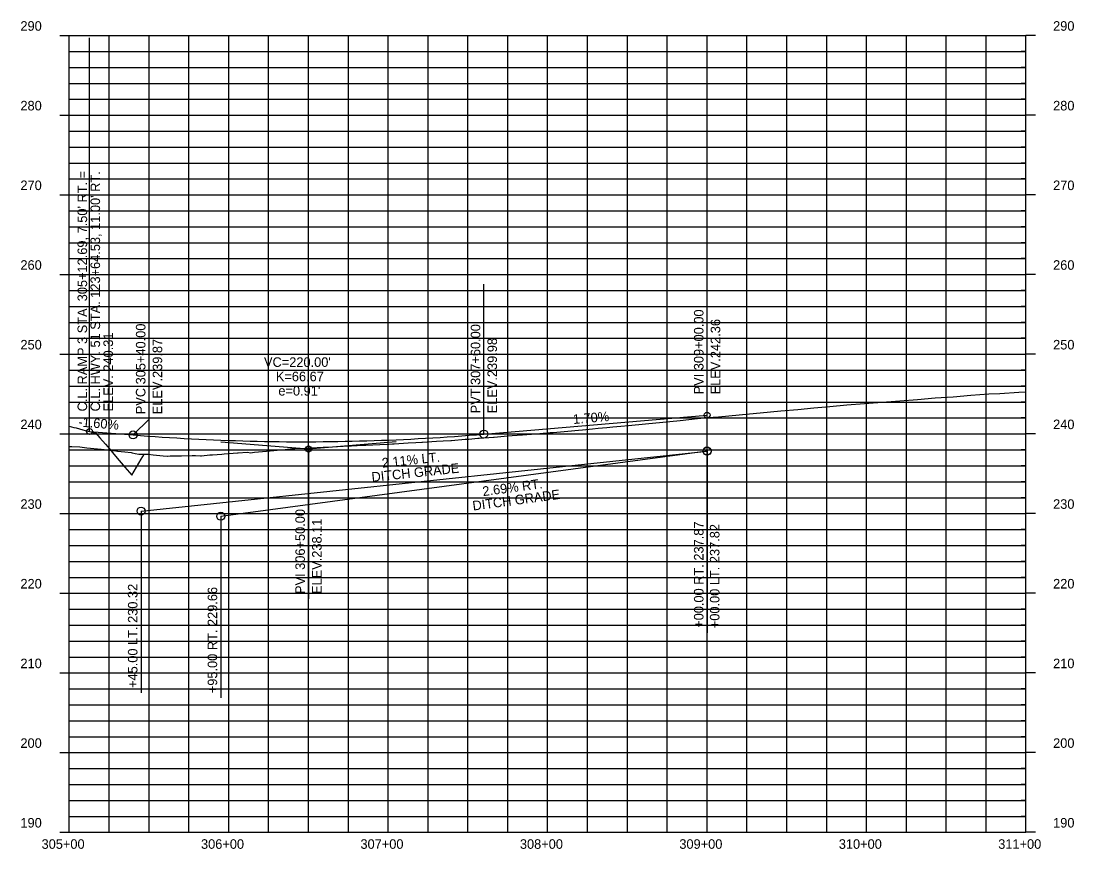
# Model space of a CAD drawing. Extents: x 921603 to 924670, y 1759276 to 1766491.
# Drawn here: x 921610 to 922270, y 1761922 to 1762441 of the extents above; entities that cross this region are included whole.
import ezdxf

# ---------------------------------------------------------------- set-up
doc = ezdxf.new("R2010")
doc.units = 0
for name, color, linetype in [('63', 7, 'Continuous'), ('R_Axis_Annotation', 7, 'Continuous'), ('R_Exist Surface', 7, 'Continuous'), ('R_Grid', 7, 'Continuous'), ('R_Grid Annot', 7, 'Continuous'), ('R_Grid_Minor', 7, 'Continuous'), ('R_Prop Surface', 7, 'Continuous'), ('R_Vert Alg', 7, 'Continuous'), ('R_Vert Alg Annot', 7, 'Continuous')]:
    doc.layers.add(name, color=color, linetype=linetype)

msp = doc.modelspace()

# ---------------------------------------------------------------- linework, layer by layer
at = {"layer": 'R_Exist Surface'}
msp.add_lwpolyline([(921639.83, 1762174.4), (921641.47, 1762174.35), (921646.42, 1762174.12), (921650.91, 1762173.53), (921659.7, 1762172.76), (921669.09, 1762171.62), (921669.17, 1762171.61), (921669.35, 1762171.59), (921670.13, 1762171.53), (921674.61, 1762171.07), (921678.69, 1762170.66), (921679.22, 1762170.5), (921681.17, 1762170.04), (921683.5, 1762169.65), (921683.64, 1762169.62), (921689.18, 1762169.57), (921692.39, 1762169.23), (921698.65, 1762168.58), (921701.28, 1762168.4), (921701.33, 1762168.4), (921703.16, 1762168.49), (921710.18, 1762168.59), (921716.79, 1762168.68), (921719.07, 1762168.65), (921722.13, 1762168.61), (921722.82, 1762168.54), (921727.96, 1762169.06), (921729.61, 1762169.22), (921735.54, 1762169.66), (921736.85, 1762169.76), (921745.32, 1762170.37), (921745.74, 1762170.4), (921751.33, 1762170.79), (921753.57, 1762170.46), (921754.63, 1762170.57), (921756.01, 1762170.71), (921763.53, 1762171.49), (921768.2, 1762171.95), (921772.42, 1762172.33), (921775.2, 1762172.57), (921779.85, 1762173.04), (921781.31, 1762173.1), (921787.44, 1762173.35), (921790.2, 1762173.48), (921791.52, 1762173.55), (921799.09, 1762173.9), (921802.11, 1762174.03), (921807.7, 1762174.28), (921807.98, 1762174.3), (921815.23, 1762174.73), (921816.87, 1762174.8), (921824.2, 1762175.13), (921825.11, 1762175.19), (921825.77, 1762175.22), (921834.66, 1762175.63), (921840.18, 1762175.88), (921842.58, 1762176.04), (921843.55, 1762176.1), (921852.44, 1762176.68), (921857.06, 1762176.98), (921861.02, 1762177.15), (921861.33, 1762177.17), (921870.22, 1762177.74), (921874.21, 1762178), (921879.12, 1762178.21), (921879.46, 1762178.22), (921888.01, 1762178.87), (921890.45, 1762179.06), (921896.05, 1762179.51), (921896.9, 1762179.58), (921905.79, 1762180.26), (921906.22, 1762180.3), (921912.6, 1762180.82), (921914.68, 1762180.97), (921923.57, 1762181.62), (921924, 1762181.65), (921932.46, 1762182.41), (921932.55, 1762182.42), (921941.36, 1762183.07), (921943.26, 1762183.22), (921950.25, 1762183.85), (921952.49, 1762184.05), (921959.14, 1762184.67), (921961.65, 1762184.91), (921968.03, 1762185.5), (921971.48, 1762185.82), (921976.92, 1762186.33), (921980.8, 1762186.7), (921985.81, 1762187.17), (921990.46, 1762187.6), (922001.25, 1762188.59), (922012.13, 1762189.74), (922022.93, 1762190.73), (922033.8, 1762191.87), (922040.32, 1762192.48), (922046.89, 1762193.08), (922053.43, 1762193.69), (922059.99, 1762194.29), (922066.53, 1762194.9), (922073.09, 1762195.5), (922079.64, 1762196.11), (922086.18, 1762196.7), (922096.65, 1762197.69), (922106.78, 1762198.62), (922116.91, 1762199.56), (922127.38, 1762200.55), (922138.52, 1762201.43), (922149.56, 1762202.25), (922160.65, 1762203.13), (922171.73, 1762203.95), (922182.81, 1762204.81), (922194.13, 1762205.64), (922205.2, 1762206.5), (922216.54, 1762207.33), (922223.4, 1762207.73), (922235.42, 1762208.39), (922239.83, 1762208.65)], dxfattribs=at)
at = {"layer": 'R_Grid'}
for p, q in [((921639.83, 1761932.26), (921639.83, 1762432.26)), ((921639.83, 1762432.26), (922239.83, 1762432.26)), ((921639.83, 1762432.26), (922239.83, 1762432.26)), ((921739.83, 1761932.26), (921739.83, 1762432.26)), ((921839.83, 1761932.26), (921839.83, 1762432.26)), ((921939.83, 1761932.26), (921939.83, 1762432.26)), ((922039.83, 1761932.26), (922039.83, 1762432.26)), ((922139.83, 1761932.26), (922139.83, 1762432.26)), ((922239.83, 1761932.26), (922239.83, 1762432.26)), ((921639.83, 1762382.26), (922239.83, 1762382.26)), ((921639.83, 1762332.26), (922239.83, 1762332.26)), ((921639.83, 1762282.26), (922239.83, 1762282.26)), ((921639.83, 1762232.26), (922239.83, 1762232.26)), ((921639.83, 1762182.26), (922239.83, 1762182.26)), ((921639.83, 1762132.26), (922239.83, 1762132.26)), ((921639.83, 1762082.26), (922239.83, 1762082.26)), ((921639.83, 1762032.26), (922239.83, 1762032.26)), ((921639.83, 1761982.26), (922239.83, 1761982.26)), ((921639.83, 1761932.26), (922239.83, 1761932.26))]:
    msp.add_line(p, q, dxfattribs=at)
at = {"layer": 'R_Grid Annot'}
for p, q in [((921633.83, 1762432.26), (921639.83, 1762432.26)), ((921633.83, 1762432.26), (921639.83, 1762432.26)), ((922245.83, 1762432.26), (922239.83, 1762432.26)), ((922245.83, 1762432.26), (922239.83, 1762432.26)), ((921639.83, 1762422.26), (921642.83, 1762422.26)), ((922239.83, 1762422.26), (922236.83, 1762422.26)), ((921639.83, 1762412.26), (921642.83, 1762412.26)), ((922239.83, 1762412.26), (922236.83, 1762412.26)), ((921639.83, 1762402.26), (921642.83, 1762402.26)), ((922239.83, 1762402.26), (922236.83, 1762402.26)), ((921639.83, 1762392.26), (921642.83, 1762392.26)), ((922239.83, 1762392.26), (922236.83, 1762392.26)), ((921633.83, 1762382.26), (921639.83, 1762382.26)), ((922245.83, 1762382.26), (922239.83, 1762382.26)), ((921639.83, 1762372.26), (921642.83, 1762372.26)), ((922239.83, 1762372.26), (922236.83, 1762372.26)), ((921639.83, 1762362.26), (921642.83, 1762362.26)), ((922239.83, 1762362.26), (922236.83, 1762362.26)), ((921639.83, 1762352.26), (921642.83, 1762352.26)), ((922239.83, 1762352.26), (922236.83, 1762352.26)), ((921639.83, 1762342.26), (921642.83, 1762342.26)), ((922239.83, 1762342.26), (922236.83, 1762342.26)), ((921633.83, 1762332.26), (921639.83, 1762332.26)), ((922245.83, 1762332.26), (922239.83, 1762332.26)), ((921639.83, 1762322.26), (921642.83, 1762322.26)), ((922239.83, 1762322.26), (922236.83, 1762322.26)), ((921639.83, 1762312.26), (921642.83, 1762312.26)), ((922239.83, 1762312.26), (922236.83, 1762312.26)), ((921639.83, 1762302.26), (921642.83, 1762302.26)), ((922239.83, 1762302.26), (922236.83, 1762302.26)), ((921639.83, 1762292.26), (921642.83, 1762292.26)), ((922239.83, 1762292.26), (922236.83, 1762292.26)), ((921633.83, 1762282.26), (921639.83, 1762282.26)), ((922245.83, 1762282.26), (922239.83, 1762282.26)), ((921639.83, 1762272.26), (921642.83, 1762272.26)), ((922239.83, 1762272.26), (922236.83, 1762272.26)), ((921639.83, 1762262.26), (921642.83, 1762262.26)), ((922239.83, 1762262.26), (922236.83, 1762262.26)), ((921639.83, 1762252.26), (921642.83, 1762252.26)), ((922239.83, 1762252.26), (922236.83, 1762252.26)), ((921639.83, 1762242.26), (921642.83, 1762242.26)), ((922239.83, 1762242.26), (922236.83, 1762242.26)), ((921633.83, 1762232.26), (921639.83, 1762232.26)), ((922245.83, 1762232.26), (922239.83, 1762232.26)), ((921639.83, 1762222.26), (921642.83, 1762222.26)), ((922239.83, 1762222.26), (922236.83, 1762222.26)), ((921639.83, 1762212.26), (921642.83, 1762212.26)), ((922239.83, 1762212.26), (922236.83, 1762212.26)), ((921639.83, 1762202.26), (921642.83, 1762202.26)), ((922239.83, 1762202.26), (922236.83, 1762202.26)), ((921639.83, 1762192.26), (921642.83, 1762192.26)), ((922239.83, 1762192.26), (922236.83, 1762192.26)), ((921633.83, 1762182.26), (921639.83, 1762182.26)), ((922245.83, 1762182.26), (922239.83, 1762182.26)), ((921639.83, 1762172.26), (921642.83, 1762172.26)), ((922239.83, 1762172.26), (922236.83, 1762172.26)), ((921639.83, 1762162.26), (921642.83, 1762162.26)), ((922239.83, 1762162.26), (922236.83, 1762162.26)), ((921639.83, 1762152.26), (921642.83, 1762152.26)), ((922239.83, 1762152.26), (922236.83, 1762152.26)), ((921639.83, 1762142.26), (921642.83, 1762142.26)), ((922239.83, 1762142.26), (922236.83, 1762142.26)), ((921633.83, 1762132.26), (921639.83, 1762132.26)), ((922245.83, 1762132.26), (922239.83, 1762132.26)), ((921639.83, 1762122.26), (921642.83, 1762122.26)), ((922239.83, 1762122.26), (922236.83, 1762122.26)), ((921639.83, 1762112.26), (921642.83, 1762112.26)), ((922239.83, 1762112.26), (922236.83, 1762112.26)), ((921639.83, 1762102.26), (921642.83, 1762102.26)), ((922239.83, 1762102.26), (922236.83, 1762102.26)), ((921639.83, 1762092.26), (921642.83, 1762092.26)), ((922239.83, 1762092.26), (922236.83, 1762092.26)), ((921633.83, 1762082.26), (921639.83, 1762082.26)), ((922245.83, 1762082.26), (922239.83, 1762082.26)), ((921639.83, 1762072.26), (921642.83, 1762072.26)), ((922239.83, 1762072.26), (922236.83, 1762072.26)), ((921639.83, 1762062.26), (921642.83, 1762062.26)), ((922239.83, 1762062.26), (922236.83, 1762062.26)), ((921639.83, 1762052.26), (921642.83, 1762052.26)), ((922239.83, 1762052.26), (922236.83, 1762052.26)), ((921639.83, 1762042.26), (921642.83, 1762042.26)), ((922239.83, 1762042.26), (922236.83, 1762042.26)), ((921633.83, 1762032.26), (921639.83, 1762032.26)), ((922245.83, 1762032.26), (922239.83, 1762032.26)), ((921639.83, 1762022.26), (921642.83, 1762022.26)), ((922239.83, 1762022.26), (922236.83, 1762022.26)), ((921639.83, 1762012.26), (921642.83, 1762012.26)), ((922239.83, 1762012.26), (922236.83, 1762012.26)), ((921639.83, 1762002.26), (921642.83, 1762002.26)), ((922239.83, 1762002.26), (922236.83, 1762002.26)), ((921639.83, 1761992.26), (921642.83, 1761992.26)), ((922239.83, 1761992.26), (922236.83, 1761992.26)), ((921633.83, 1761982.26), (921639.83, 1761982.26)), ((922245.83, 1761982.26), (922239.83, 1761982.26)), ((921639.83, 1761972.26), (921642.83, 1761972.26)), ((922239.83, 1761972.26), (922236.83, 1761972.26)), ((921639.83, 1761962.26), (921642.83, 1761962.26)), ((922239.83, 1761962.26), (922236.83, 1761962.26)), ((921639.83, 1761952.26), (921642.83, 1761952.26)), ((922239.83, 1761952.26), (922236.83, 1761952.26)), ((921639.83, 1761942.26), (921642.83, 1761942.26)), ((922239.83, 1761942.26), (922236.83, 1761942.26)), ((921633.83, 1761932.26), (921639.83, 1761932.26)), ((922245.83, 1761932.26), (922239.83, 1761932.26))]:
    msp.add_line(p, q, dxfattribs=at)
at = {"layer": 'R_Grid_Minor'}
for p, q in [((921664.83, 1761932.26), (921664.83, 1762432.26)), ((921689.83, 1761932.26), (921689.83, 1762432.26)), ((921714.83, 1761932.26), (921714.83, 1762432.26)), ((921764.83, 1761932.26), (921764.83, 1762432.26)), ((921789.83, 1761932.26), (921789.83, 1762432.26)), ((921814.83, 1761932.26), (921814.83, 1762432.26)), ((921864.83, 1761932.26), (921864.83, 1762432.26)), ((921889.83, 1761932.26), (921889.83, 1762432.26)), ((921914.83, 1761932.26), (921914.83, 1762432.26)), ((921964.83, 1761932.26), (921964.83, 1762432.26)), ((921989.83, 1761932.26), (921989.83, 1762432.26)), ((922014.83, 1761932.26), (922014.83, 1762432.26)), ((922064.83, 1761932.26), (922064.83, 1762432.26)), ((922089.83, 1761932.26), (922089.83, 1762432.26)), ((922114.83, 1761932.26), (922114.83, 1762432.26)), ((922164.83, 1761932.26), (922164.83, 1762432.26)), ((922189.83, 1761932.26), (922189.83, 1762432.26)), ((922214.83, 1761932.26), (922214.83, 1762432.26)), ((921639.83, 1762422.26), (922239.83, 1762422.26)), ((921639.83, 1762412.26), (922239.83, 1762412.26)), ((921639.83, 1762402.26), (922239.83, 1762402.26)), ((921639.83, 1762392.26), (922239.83, 1762392.26)), ((921639.83, 1762372.26), (922239.83, 1762372.26)), ((921639.83, 1762362.26), (922239.83, 1762362.26)), ((921639.83, 1762352.26), (922239.83, 1762352.26)), ((921639.83, 1762342.26), (922239.83, 1762342.26)), ((921639.83, 1762322.26), (922239.83, 1762322.26)), ((921639.83, 1762312.26), (922239.83, 1762312.26)), ((921639.83, 1762302.26), (922239.83, 1762302.26)), ((921639.83, 1762292.26), (922239.83, 1762292.26)), ((921639.83, 1762272.26), (922239.83, 1762272.26)), ((921639.83, 1762262.26), (922239.83, 1762262.26)), ((921639.83, 1762252.26), (922239.83, 1762252.26)), ((921639.83, 1762242.26), (922239.83, 1762242.26)), ((921639.83, 1762222.26), (922239.83, 1762222.26)), ((921639.83, 1762212.26), (922239.83, 1762212.26)), ((921639.83, 1762202.26), (922239.83, 1762202.26)), ((921639.83, 1762192.26), (922239.83, 1762192.26)), ((921639.83, 1762172.26), (922239.83, 1762172.26)), ((921639.83, 1762162.26), (922239.83, 1762162.26)), ((921639.83, 1762152.26), (922239.83, 1762152.26)), ((921639.83, 1762142.26), (922239.83, 1762142.26)), ((921639.83, 1762122.26), (922239.83, 1762122.26)), ((921639.83, 1762112.26), (922239.83, 1762112.26)), ((921639.83, 1762102.26), (922239.83, 1762102.26)), ((921639.83, 1762092.26), (922239.83, 1762092.26)), ((921639.83, 1762072.26), (922239.83, 1762072.26)), ((921639.83, 1762062.26), (922239.83, 1762062.26)), ((921639.83, 1762052.26), (922239.83, 1762052.26)), ((921639.83, 1762042.26), (922239.83, 1762042.26)), ((921639.83, 1762022.26), (922239.83, 1762022.26)), ((921639.83, 1762012.26), (922239.83, 1762012.26)), ((921639.83, 1762002.26), (922239.83, 1762002.26)), ((921639.83, 1761992.26), (922239.83, 1761992.26)), ((921639.83, 1761972.26), (922239.83, 1761972.26)), ((921639.83, 1761962.26), (922239.83, 1761962.26)), ((921639.83, 1761952.26), (922239.83, 1761952.26)), ((921639.83, 1761942.26), (922239.83, 1761942.26))]:
    msp.add_line(p, q, dxfattribs=at)
at = {"layer": 'R_Prop Surface'}
msp.add_lwpolyline([(921639.83, 1762187.09), (921641.26, 1762186.72), (921642.58, 1762186.38), (921642.68, 1762186.35), (921642.7, 1762186.35), (921644.12, 1762185.98), (921648.3, 1762184.9), (921652.47, 1762183.82), (921652.49, 1762183.82), (921652.52, 1762183.81), (921656.55, 1762182.77), (921659.06, 1762179.81), (921662.42, 1762175.84), (921663.89, 1762174.11), (921669.9, 1762167.01), (921674.79, 1762161.26), (921675.91, 1762159.94), (921676.05, 1762159.77), (921676.16, 1762159.64), (921678.97, 1762156.33), (921684.94, 1762166.37), (921685.99, 1762168.13), (921686.86, 1762169.59)], dxfattribs=at)
at = {"layer": 'R_Vert Alg'}
for p, q in [((921899.83, 1762182.17), (922039.83, 1762194.07)), ((921652.52, 1762183.81), (921679.83, 1762181.62)), ((921684.83, 1762133.86), (922039.83, 1762171.36)), ((921734.83, 1762130.56), (922039.83, 1762171.61))]:
    msp.add_line(p, q, dxfattribs=at)
msp.add_lwpolyline([(921679.83, 1762181.62), (921684.41, 1762181.27), (921688.99, 1762180.92), (921693.58, 1762180.6), (921698.16, 1762180.28), (921702.74, 1762179.99), (921707.33, 1762179.71), (921711.91, 1762179.44), (921716.49, 1762179.2), (921721.08, 1762178.96), (921725.66, 1762178.75), (921730.24, 1762178.54), (921734.83, 1762178.36), (921739.41, 1762178.19), (921743.99, 1762178.04), (921748.58, 1762177.9), (921753.16, 1762177.77), (921757.74, 1762177.67), (921762.33, 1762177.58), (921766.91, 1762177.5), (921771.49, 1762177.44), (921776.08, 1762177.4), (921780.66, 1762177.37), (921785.24, 1762177.36), (921794.41, 1762177.38), (921798.99, 1762177.42), (921803.58, 1762177.47), (921808.16, 1762177.53), (921812.74, 1762177.62), (921817.33, 1762177.71), (921821.91, 1762177.83), (921826.49, 1762177.96), (921831.08, 1762178.1), (921835.66, 1762178.26), (921840.24, 1762178.44), (921844.83, 1762178.63), (921849.41, 1762178.84), (921853.99, 1762179.07), (921858.58, 1762179.31), (921863.16, 1762179.56), (921867.74, 1762179.83), (921872.33, 1762180.12), (921876.91, 1762180.42), (921881.49, 1762180.74), (921886.08, 1762181.08), (921890.66, 1762181.43), (921895.24, 1762181.79), (921899.83, 1762182.17)], dxfattribs=at)
at = {"layer": 'R_Vert Alg Annot'}
for p, q in [((921652.52, 1762193.81), (921652.52, 1762430.83)), ((922039.83, 1762204.07), (922039.83, 1762288.07)), ((921689.83, 1762191.62), (921689.83, 1762275.62)), ((921899.83, 1762192.17), (921899.83, 1762276.17)), ((922039.83, 1762194.07), (922039.83, 1762204.07)), ((921652.52, 1762183.81), (921652.52, 1762193.81)), ((921679.83, 1762181.62), (921689.83, 1762191.62)), ((921899.83, 1762182.17), (921899.83, 1762192.17)), ((921789.83, 1762172.82), (921844.83, 1762177.5)), ((921734.83, 1762177.22), (921789.83, 1762172.82)), ((921789.83, 1762172.82), (921789.83, 1762162.82)), ((922039.83, 1762171.61), (922039.83, 1762141.61)), ((922039.83, 1762171.36), (922039.83, 1762141.36)), ((921789.83, 1762162.82), (921789.83, 1762078.82)), ((922039.83, 1762141.61), (922039.83, 1762057.61)), ((922039.83, 1762141.36), (922039.83, 1762057.36)), ((921684.83, 1762133.86), (921684.83, 1762103.86)), ((921734.83, 1762130.56), (921734.83, 1762100.56)), ((921684.83, 1762103.86), (921684.83, 1762019.86)), ((921734.83, 1762100.56), (921734.83, 1762016.56))]:
    msp.add_line(p, q, dxfattribs=at)
for centre, radius in [((922039.83, 1762194.07), 1.85), ((921652.52, 1762183.81), 1.85), ((921679.83, 1762181.62), 2.5), ((921899.83, 1762182.17), 2.5), ((921789.83, 1762172.82), 1.85), ((922039.83, 1762171.61), 2.5), ((922039.83, 1762171.36), 2.5), ((921684.83, 1762133.86), 2.5), ((921734.83, 1762130.56), 2.5)]:
    msp.add_circle(centre, radius, dxfattribs=at)

# ---------------------------------------------------------------- texts
at = {"layer": '63'}
msp.add_text('-', height=0.0001, dxfattribs=at).set_placement((921639.83, 1761932.26))
at = {"layer": 'R_Axis_Annotation'}
for s, p in [('290', (921609.16, 1762435.26)), ('290', (921609.16, 1762435.26)), ('290', (922256.84, 1762435.26)), ('290', (922256.84, 1762435.26)), ('280', (921609.16, 1762385.26)), ('280', (922256.84, 1762385.26)), ('270', (921609.16, 1762335.26)), ('270', (922256.84, 1762335.26)), ('260', (921609.16, 1762285.26)), ('260', (922256.84, 1762285.26)), ('250', (921609.16, 1762235.26)), ('250', (922256.84, 1762235.26)), ('240', (921609.16, 1762185.26)), ('240', (922256.84, 1762185.26)), ('230', (921609.16, 1762135.26)), ('230', (922256.84, 1762135.26)), ('220', (921609.16, 1762085.26)), ('220', (922256.84, 1762085.26)), ('210', (921609.16, 1762035.26)), ('210', (922256.84, 1762035.26)), ('200', (921609.16, 1761985.26)), ('200', (922256.84, 1761985.26)), ('190', (921609.16, 1761935.26)), ('190', (922256.84, 1761935.26)), ('305+00', (921622.42, 1761921.91)), ('306+00', (921722.42, 1761921.91)), ('307+00', (921822.42, 1761921.91)), ('308+00', (921922.42, 1761921.91)), ('309+00', (922022.42, 1761921.91)), ('310+00', (922122.42, 1761921.91)), ('311+00', (922222.42, 1761921.91))]:
    msp.add_text(s, height=6, dxfattribs=at).set_placement(p)
at = {"layer": 'R_Vert Alg Annot'}
for s, rotation, p in [("C.L. RAMP 3 STA. 305+12.69, 7.50' RT. =", 90, (921650.99, 1762196.37)), ("C.L. HWY. 51 STA. 123+64.53, 11.00' RT.", 90, (921659.12, 1762196.37)), ('PVI 309+00.00', 90, (922037.58, 1762207.07)), ('PVC 305+40.00', 90, (921687.58, 1762194.62)), ('PVT 307+60.00', 90, (921897.58, 1762195.17)), ('ELEV.242.36', 90, (922048.08, 1762207.07)), ('ELEV. 240.31', 90, (921667.25, 1762196.37)), ('ELEV.239.87', 90, (921698.08, 1762194.62)), ('ELEV.239.98', 90, (921908.08, 1762195.17)), ('-1.60%', 355.42608, (921645.31, 1762186.93)), ('1.70%', 4.85846, (921955.95, 1762188.45)), ('2.11% LT. ', 6.03001, (921836.17, 1762161.04)), ('DITCH GRADE', 6.03001, (921829.69, 1762152.18)), ('2.69% RT. ', 7.66594, (921899.36, 1762143.19)), ('DITCH GRADE', 7.66594, (921893.13, 1762134.15)), ('PVI 306+50.00', 90, (921787.58, 1762081.82)), ('ELEV.238.11', 90, (921798.08, 1762081.82)), ('+00.00 RT. 237.87', 90, (922037.58, 1762060.61)), ('+00.00 LT. 237.82', 90, (922047.58, 1762060.36)), ('+45.00 LT. 230.32', 90, (921682.58, 1762022.86)), ('+95.00 RT. 229.66', 90, (921732.58, 1762019.56))]:
    msp.add_text(s, height=6, rotation=rotation, dxfattribs=at).set_placement(p)
for s, p in [("VC=220.00'", (921761.93, 1762224.33)), ('K=66.67', (921769.35, 1762215.33)), ("e=0.91'", (921770.93, 1762206.33))]:
    msp.add_text(s, height=6, dxfattribs=at).set_placement(p)

doc.saveas('drawing.dxf')
